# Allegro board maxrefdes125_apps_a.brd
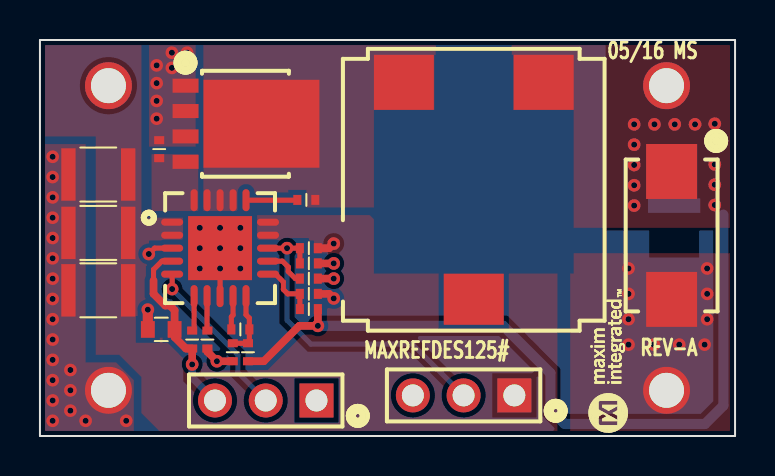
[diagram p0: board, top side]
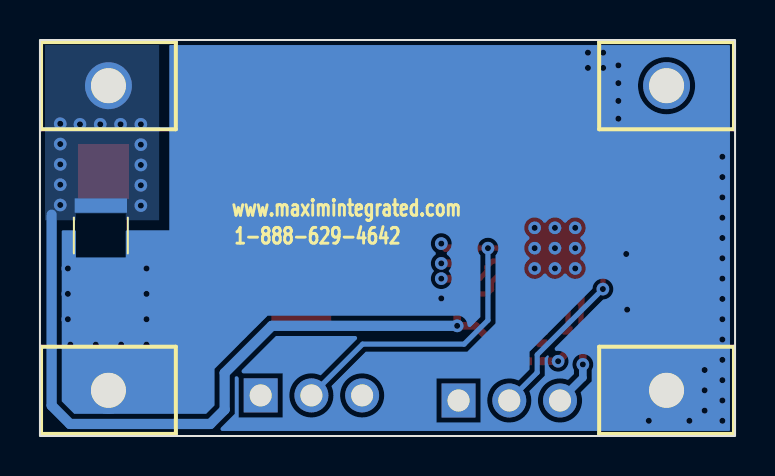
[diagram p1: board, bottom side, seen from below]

Outline 34.8 x 19.81 mm; copper layers: TOP, INTERNAL2, INTERNAL3, BOTTOM. Coordinates in mm from the lower left corner of the outline.
Outline path: rectangle 0,0 34.8,19.81

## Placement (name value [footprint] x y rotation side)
C1  2.2UF  [1210]  2.92 13.08 0 top
C2  2.2UF  [1210]  2.92 10.16 0 top
C3  OPEN  [1210]  2.92 7.29 0 top
C5  2.2UF  [0603]  6.07 5.33 0 top
C6  0.022UF  [0402]  13.46 7.87 0 top
C7  120UF  [CAPMP7343X310M]  31.62 10.03 270 top
C8  22UF  [1210]  31.75 10.03 90 bottom
C9  0.1UF  [0402]  13.34 11.81 0 top
C10  2.2PF  [0402]  10.03 5.33 180 top
C11  0.1UF  [0402]  13.46 7.11 180 top
EV_KIT_BOX2  MEDIUM BOX  [EVKIT_PACKAGING]  34.16 -5.33 0 top
GNDO  FWJ-01-01-T-S  [SAMTEC_FWJ-01-01-X-X]  31.37 2.29 270 bottom
JU1  PEC03SAAN  [SULLINS_PXC03S]  13.84 1.78 180 top
JU2  PEC03SAAN  [SULLINS_PXC03S]  23.75 2.03 180 top
L1  10UH  [IND_CEP125NP]  21.72 12.32 270 top
N1  RJK0651DPB-00#J5  [TO127P600X110-5M]  10.29 15.62 0 top
NOREF  -  []  25.15 52.2 0 top
NOREF#2  -  []  -12.19 19.81 0 top
NOREF#3  -  []  28.45 1.14 90 top
NOREF#4  -  []  47.37 19.81 0 top
NOREF#5  -  []  34.8 0 90 top
NOREF#6  -  []  124.71 -17.53 0 top
NOREF#7  -  []  46.86 0 0 top
NOREF#8  -  []  0 19.81 0 top
NOREF#9  -  []  12.7 -6.6 0 top
PGND  FWJ-01-01-T-S  [SAMTEC_FWJ-01-01-X-X]  3.43 2.29 270 bottom
R1  3.32M  [0402]  13.46 9.4 180 top
R2  300K  [0402]  13.46 8.64 0 top
R3  169K  [0402]  10.41 4.19 270 top
R4  36K  [0402]  9.65 4.19 270 top
R5  93.1K  [0402]  8.38 4.83 270 top
R6  10K  [0402]  7.62 4.83 90 top
R7  OPEN  [0402]  5.97 14.35 270 top
R8  4.7  [0402]  13.46 6.35 0 top
SU1  STC02SYAN  [EVKIT_SHUNT]  34.29 -12.32 0 top
SU2  STC02SYAN  [EVKIT_SHUNT]  34.16 -19.68 0 top
U1  MAX17536ATP+  [QFN65P500X500X80-21M]  9.02 9.4 0 top
VIN  FWJ-01-01-T-S  [SAMTEC_FWJ-01-01-X-X]  3.43 17.53 90 bottom
VOUT  FWJ-01-01-T-S  [SAMTEC_FWJ-01-01-X-X]  31.37 17.53 90 bottom

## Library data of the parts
C1 C2 = CAP_NP: alternate symbols: CAPC3225X270L; part number: CAP_NP_1210CAP-1210,2.2UF,20-002U2-Q1
C3 = EVK_GENERIC_CAPACITORS: alternate symbols: CAPC3225X270L; part number: EVK_GENERIC_CAPACITORS_1210CAP-1210,N/A
C5 = CAP_NP: alternate symbols: 0603_NOSILK,CAPC1608X90L; part number: CAP_NP_0603CAP-0603,2.2UF,20-002U2-10
C6 = CAP_NP: alternate symbols: 0402_NOSILK,CAPC1005X50L; part number: CAP_NP_0402CAP-0402,0.022UF,20-0U022-B60
C7 = CAP_POL: part number: CAP_POL_7343CAP-CAPMP7343X310M,120UF,20-0120U-J3A
C8 = CAP_NP: alternate symbols: CAPC3225X270L; part number: CAP_NP_1210CAP-1210,22UF,20-0022U-T7A
C9 C11 = CAP_NP: alternate symbols: 0402_NOSILK,CAPC1005X50L; part number: CAP_NP_0402CAP-0402,0.1UF,20-000U1-04A
C10 = CAP_NP: alternate symbols: 0402_NOSILK,CAPC1005X50L; part number: CAP_NP_0402CAP-0402,2.2PF,20-002P2-X1B
EV_KIT_BOX2 = EV_KIT_BOX: part number: EV_KIT_BOX_ACCESSORY-N/A,MEDIUM BOX,EVKIT_PACKAGING
GNDO PGND VIN VOUT = HEADER_1P: part number: HEADER_1P_TH-SAMTEC_FWJ-01-01-X-X,FWJ-01-01-T-S,01-FWJ0101TS1P-19
JU1 JU2 = HEADER_3P: alternate symbols: SULLINS_PXC03SL; part number: HEADER_3P_PXC03S-SULLINS_PXC03S,PEC03SAAN,01-PEC03SAAN3P-21
L1 = INDUCTOR_3P: part number: INDUCTOR_3P_IND_CEP125NP-IND_CEP125NP,10UH,50-0010U-0JG
N1 = TRAN_NCH_5P: part number: TRAN_NCH_5P_LFPAK-TO127P600X110-5M,RJK0651DPB-00#J5,90-RJK0651DPB00J5-21
R1 = RES: alternate symbols: (0402_NOSILK,RESC1005X50L); part number: RES_0402RES-0402,3.32M,80-03M32-23
R2 = RES: alternate symbols: (0402_NOSILK,RESC1005X50L); part number: RES_0402RES-0402,300K,80-0300K-23
R3 = RES: alternate symbols: (0402_NOSILK,RESC1005X50L); part number: RES_0402RES-0402,169K,80-0169K-23
R4 = RES: alternate symbols: 0402_NOSILK,RESC1005X50L; part number: RES_0402RES-0402,36K,80-0036K-18
R5 = RES: alternate symbols: (0402_NOSILK,RESC1005X50L); part number: RES_0402RES-0402,93.1K,80-093K1-23
R6 = RES: alternate symbols: 0402_NOSILK,RESC1005X50L; part number: RES_0402RES-0402,10K,80-0010K-23
R7 = EVK_GENERIC_RESISTORS: alternate symbols: 0402_NOSILK,RESC1005X50L; part number: EVK_GENERIC_RESISTORS_0402RES-0402,N/A
R8 = RES: alternate symbols: (0402_NOSILK,RESC1005X50L); part number: RES_0402RES-0402,4.7,80-004R7-23
SU1 SU2 = SHUNT: part number: SHUNT_SHUNT_2P-02-JMPFSTC02SYAN-00,STC02SYAN,EVKIT_SHUNT
U1 = EK_MAX17536: part number: EK_MAX17536_TQFN20-EP-QFN65P500X500X80-21M,MAX17536ATP+,N/A

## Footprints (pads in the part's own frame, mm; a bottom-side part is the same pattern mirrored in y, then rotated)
0402
  rect 0.4x0.5 smd: 1(-0.45,0) 2(0.45,0)
0603
  rect 0.69x0.83 smd: 1(-0.67,0) 2(0.67,0)
1210
  rect 0.72x2.62 smd: 1(-1.495,0) 2(1.495,0)
CAPMP7343X310M
  rect 2.75x2.55 smd: 1(-3.2,0) 2(3.2,0)
IND_CEP125NP
  rect 2.75x3 smd: 1(-5.375,3.5) 2(-5.375,-3.5)
  rect 2.55x3 smd: 3(5.475,0)
QFN65P500X500X80-21M
  oval 1.1x0.35 smd: 1(-2.4,1.3) 2(-2.4,0.65) 3(-2.4,0) 4(-2.4,-0.65) 5(-2.4,-1.3) 11(2.4,-1.3) 12(2.4,-0.65) 13(2.4,0) 14(2.4,0.65) 15(2.4,1.3)
  oval 0.35x1.1 smd: 6(-1.3,-2.4) 7(-0.65,-2.4) 8(0,-2.4) 9(0.65,-2.4) 10(1.3,-2.4) 16(1.3,2.4) 17(0.65,2.4) 18(0,2.4) 19(-0.65,2.4) 20(-1.3,2.4)
  rect 3.2x3.2 smd: 21(0,0)
SAMTEC_FWJ-01-01-X-X
  round 2.35 hole 1.75: 1(0,0)
SULLINS_PXC03S
  rect 1.7x1.7 hole 1.1: 1(0,0)
  round 1.7 hole 1.1: 2(2.54,0) 3(5.08,0)
TO127P600X110-5M
  rect 1.3x0.7 smd: 1(-3,1.905) 2(-3,0.635) 3(-3,-0.635) 4(-3,-1.905)
  rect 5.8x4.4 smd: 5(0.8,0)

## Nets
PGND: C1.1 C2.1 C3.1 C7.2(B) C8.1 C11.1 GNDO.1 N1.1(S1) N1.2(S2) N1.3(S3) PGND.1 R7.1 U1.3(PGND)
SGND: C5.1 C6.2 JU1.1 JU2.3 R2.2 R4.2 R5.2 U1.8(SGND) U1.21(EP)
VCC: C5.2 JU1.3 R6.1 U1.4(VCC)
VIN: C1.2 C2.2 C3.2 JU2.1 R1.1 U1.1(VIN_1) U1.2(VIN_2) U1.14(VIN_3) U1.15(VIN_4) VIN.1
UNNAMED_1_CAPNP_I5_2: C11.2 R8.1 U1.11(EXTVCC)
UNNAMED_1_CAPNP_I8_1: C6.1 U1.12(SS)
UNNAMED_1_CAPNP_I36_1: C9.1 U1.16(BST)
UNNAMED_1_CAPNP_I36_2: C9.2 L1.2 N1.5(D) U1.17(LX_1) U1.18(LX_2) U1.19(LX_3)
UNNAMED_1_CAPNP_I47_1: C10.1 R3.1 R4.1 U1.10(FB)
UNNAMED_1_CAPNP_I47_2: C10.2 U1.9(CF)
UNNAMED_1_EKMAX17536_I1_DL: N1.4(G) R7.2 U1.20(DL)
UNNAMED_1_EKMAX17536_I1_EN: JU2.2 R1.2 R2.1 U1.13(EN/UVLO)
UNNAMED_1_EKMAX17536_I1_MODE: JU1.2 U1.5(MODE/SYNC)
UNNAMED_1_EKMAX17536_I1_RESETB: R6.2 U1.6(RESETB)
UNNAMED_1_EKMAX17536_I1_RT: R5.1 U1.7(RT)
VOUT: C7.1(A) C8.2 L1.1 R3.2 R8.2 VOUT.1

Pads without a net: L1 3

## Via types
v1: diameter 0.635, hole 0.305, TOP to BOTTOM, 70 vias

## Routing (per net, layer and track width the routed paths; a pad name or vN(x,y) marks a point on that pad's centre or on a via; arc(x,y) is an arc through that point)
PGND: length 2.2
  TOP w0.254: v1(5.45,9.11) 5.74,9.4 U1.3
  TOP w0.381: v1(14.71,6.88) 14.48,7.11 C11.1
  vias: v1(0.64,13.97) v1(0.64,12.95) v1(0.64,11.94) v1(0.64,10.92) v1(0.64,9.91) v1(0.64,8.89) v1(0.64,7.87) v1(0.64,6.86) v1(0.64,5.84) v1(0.64,4.83) v1(0.64,3.81) v1(0.64,2.79) v1(0.64,1.78) v1(0.64,0.76) v1(1.52,3.3) v1(1.52,2.29) v1(1.52,1.27) v1(2.29,0.76) v1(4.32,0.76) v1(5.84,18.54) v1(5.84,17.65) v1(5.84,16.76) v1(5.84,15.88) v1(6.6,19.18) v1(6.6,18.41) v1(7.37,19.18) v1(7.37,18.41) v1(29.46,8.38) v1(29.46,7.11) v1(29.46,5.84) v1(29.46,4.57) v1(30.73,4.57) v1(32,4.57) v1(33.27,4.57) v1(33.4,8.38) v1(33.4,7.11) v1(33.4,5.84)
SGND: length 5.6
  TOP w0.254: v1(9.02,8.38) U1.8
  TOP w0.381: R5.2 8.38,4.22 v1(8.86,3.74) R4.2 ; C6.2 v1(14.71,7.87) ; R2.2 v1(14.71,8.64)
  TOP w0.508: C5.1 v1(5.4,6.32)
  vias: v1(8,10.41) v1(8,9.4) v1(8,8.38) v1(9.02,10.41) v1(9.02,9.4) v1(10.03,10.41) v1(10.03,9.4) v1(10.03,8.38)
VCC: length 9.2
  TOP w0.254: 5.69,7.78 5.69,8.33 6.11,8.75 U1.4
  TOP w0.381: 5.69,7.78 5.69,7.11 6.27,6.53 6.5,6.53 6.74,6.29 C5.2 6.74,4.95 7.31,4.38 R6.1 v1(7.62,3.58)
  BOTTOM w0.381: v1(7.62,3.58) 7.62,2.92 JU1.3
VIN: length 0.9
  TOP w0.381: v1(14.71,9.63) 14.48,9.4 R1.1
UNNAMED_1_CAPNP_I5_2: length 3
  TOP w0.254: R8.1 C11.2 12.4,7.11 12.19,7.33 12.19,7.7 11.79,8.1 U1.11
UNNAMED_1_CAPNP_I8_1: length 2.1
  TOP w0.254: U1.12 12.14,8.75 12.43,8.46 12.43,8.23 12.78,7.87 C6.1
UNNAMED_1_CAPNP_I36_1: length 2.6
  TOP w0.254: C9.1 12.87,11.8 U1.16
UNNAMED_1_CAPNP_I47_1: length 3.2
  TOP w0.254: U1.10 10.32,6.07 10.48,5.9 C10.1 10.48,4.71 R3.1 R4.1
UNNAMED_1_CAPNP_I47_2: length 1.7
  TOP w0.254: U1.9 9.67,6.05 9.58,5.97 C10.2
UNNAMED_1_EKMAX17536_I1_EN: length 16.4
  TOP w0.254: R2.1 R1.2 v1(12.37,9.4) U1.13
  BOTTOM w0.254: v1(12.37,9.4) 12.37,5.79 13.56,4.6 18.64,4.6 JU2.2
UNNAMED_1_EKMAX17536_I1_MODE: length 8.3
  TOP w0.254: U1.5 v1(6.62,7.35)
  BOTTOM w0.254: v1(6.62,7.35) 9.91,4.06 9.91,3.17 JU1.2
UNNAMED_1_EKMAX17536_I1_RESETB: length 1.8
  TOP w0.254: R6.2 7.72,5.37 U1.6
UNNAMED_1_EKMAX17536_I1_RT: length 1.7
  TOP w0.254: R5.1 8.37,5.29 U1.7
VOUT: length 38.4
  TOP w0.381: R8.2 v1(13.91,5.51) 12.98,5.51 11.21,3.74 R3.2
  BOTTOM w0.508: v1(13.91,5.51) 23.19,5.51 25.55,3.15 25.55,1.32 26.27,0.6 33.29,0.6 34.21,1.52 34.21,11.08
  vias: v1(29.75,15.59) v1(29.75,14.58) v1(29.75,13.56) v1(29.75,12.54) v1(29.75,11.53) v1(30.76,15.59) v1(31.78,15.59) v1(32.79,15.59) v1(33.78,15.62) v1(33.78,14.61) v1(33.78,13.59) v1(33.78,12.57) v1(33.78,11.56)

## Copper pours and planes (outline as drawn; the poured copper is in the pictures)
PGND on BOTTOM (solid shape): outline of 995 points within 0.25,0.25 33.71,19.56
PGND on TOP: 0.25,0.25 0.25,14.61 2.29,14.61 2.29,3.68 3.81,3.68 4.7,2.79 4.7,0.25 1.91,0.25 1.91,0.25
PGND on TOP: 5.46,14.48 5.46,19.56 8,19.56 8,14.48
PGND on TOP: 26.54,0.25 26.54,9.14 34.54,9.14 34.54,0.25
SGND on INTERNAL2, INTERNAL3: 0.26,0.26 0.26,19.56 34.54,19.56 34.54,0.26 ; 1 cut-out
VIN on TOP: 5.97,0.25 2.79,3.43 2.79,14.99 0.25,14.99 0.25,19.56 5.08,19.56 5.08,10.92 7.24,10.92 7.24,9.78 5.46,9.78 5.46,6.22 8,3.68 11.68,3.68 13.72,5.71 13.72,9.78 10.79,9.78 10.79,11.05 16.51,11.05 18.8,8.76 25.91,8.76 25.91,0.25
UNNAMED_1_CAPNP_I36_2 on TOP: 8.18,11.18 8.18,19.56 19.81,19.56 19.81,13.72 17.53,11.43 10.41,11.43 10.16,11.18
UNNAMED_1_EKMAX17536_I1_DL on TOP: 7.92,11.25 7.92,14.1 5.59,14.1 5.59,11.25
VOUT on TOP: 23.62,10.41 23.62,19.56 34.54,19.56 34.54,10.41
VOUT on BOTTOM: 28.83,10.79 28.83,19.56 34.54,19.56 34.54,10.79

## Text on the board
Ref Des/Silkscreen Bottom: 1-888-629-4642 | www.maximintegrated.com
Ref Des/Silkscreen Top: MAXREFDES125# | 05/16 MS | REV-A
DIMENSION: NOTES: | FINISH: | TESTING: | MISCELLANEOUS: | TOOLING: | 16.  VENDOR LOGO & DATE CODE REQUIRED IN INK ON BOTTOM SIDE ONLY. DATE CODE FORMAT MUST BE YYWW ONLY | 17.  FINAL ELECTRICAL TEST TO BE PERFORMED USING PROVIDED IPC-D-356A NETLIST OR ODB++ FORMAT FILE. | 18.  A TIME DOMAIN REFLECTOMETER REPORT FOR EACH IMPEDANCE CONTROLLED LAYER AND A CERTIFICATE | 15.  CHECK ALL THAT APPLY | 14.  CHECK ALL THAT APPLY | 19. IF PRESENT, ALL BLIND/BURIED VIAS WITH AN ASPECT RATIO <1:1 TO BE PLATED SHUT WITH COPPER WHEN | 20.  FOR ALL DRILL INFORMATION REFER TO DRILL CHART. | 21.  FINISHED SURFACE CONTACTS AND FILLED VIAS TO BE FREE OF ANY PITS. SCRATCHES PROBE MARKS | 23.  PEMNUT | 13.  DRILL SIZES ARE FINISHED HOLE SIZES. ALL HOLES SHALL BE LOCATED WITHIN .005 DTP. | 22.  THIEVING: | 9.  ALL TRACES FILLETED OPTION TO ENHANCE RELIABILITY AT PAD JUNCTIONS | 10.  LAYER TO LAYER REGISTRATIONS SHALL BE WITHIN .003 INCHES. | MATERIAL: | 11.  PLATING SPECIFICATION: | 12.  CHECK ALL THAT APPLY | 8.  IF STATED IN THE LAMINATION DIAGRAM, THE DIELECTRIC THICKNESS OF ANY | 1.  DIMENSIONS ARE IN INCHES (EXCEPT WHERE NOTED). | 3.  THE PCB SHALL BE FABRICATED TO IPC-6012, TYPE X, CLASS 2. | 4.  BOARD MATERIAL & CONSTRUCTION SHALL MEET THE REQUIREMENTS OF UL796 | 5.  OVERALL BOARD THICKNESS REFER TO LAMINATION DIAGRAM. TOLERANCE APPLIES | 6.  BOW & TWIST NOT TO EXCEED 0.0075 IN. (0.75%) PER LINEAR INCH. | 7.  PHOTO ETCH CIRCUITRY PER ENCLOSED GERBER RS274X OR ODB++ FORMAT FILE. | 2.  BOARD MATERIAL: | ( )  FINISH CONDUCTOR SURFACES: IMMERSION GOLD, 2-5 MICRO INCHES OVER | ( )  STARTING COPPER WEIGHT FOR OUTER LAYERS TO BE (1 OZ), THE FINISH COPPER WEIGHT IS (1 OZ). | ( )  STARTING COPPER WEIGHT FOR OUTER LAYERS TO BE (1 OZ), THE FINISH COPPER WEIGHT IS (2 OZ). | (X)  STARTING COPPER WEIGHT FOR OUTER LAYERS TO BE (2 OZ), THE FINISH COPPER WEIGHT IS (2 OZ)MINIMUM. | ( )  OTHER ________________________ | (X)  FINISH CONDUCTOR SURFACES: IMMERSION GOLD, 3-8 MICRO INCHES OVER | ( )  FINGERS TO BE GOLD PLATED. | ( )  LEAD FREE AND RoHS COMPLIANT PLATING. | (X)  GREEN SOLDERMASK OVER BARE COPPER/BARE GOLD (BOTH SIDES) WITH LIQUID PHOTO IMAGEABLE INK (LPI) | ( )  GREEN TAIYO PSR-4000 | ( )  ELECTRODEPOSITED HARD GOLD PLATE, TYPE 1 (99.7% MIN GOLD), GRADE C | (X)  APPLY SILKSCREEN USING A NON-CONDUCTIVE, WHITE EPOXY | THE STARTING WEIGHT CAN BE (0.5 OZ) AS LONG AS THE FINISH COPPER WEIGHT IS (2 OZ). | THE STARTING WEIGHT CAN BE (<2 OZ) AS LONG AS THE FINISH COPPER WEIGHT IS (2 OZ). | MINIMUM BARREL PLATING OF .001 IN. PLATED HOLES SHALL NOT BE ROUGH OR IRREGULAR | SO AS TO HINDER PROPER SOLDER WICKING. | USED AS VIA-IN PAD OR AS A STACKED VIA. BLIND/BURIED VIAS WITH AN ASPECT RATIO >1:1 TO BE FILLED | WITH NON-CONDUCTIVE EPOXY. UNLESS OTHERWISE SPECIFIED. | ( )  NON-CONDUCTIVE EPOXY. FILL AND CAP ALL 0.XXXX INCH DRILLED VIAS. | ( )  SILVER. FILL AND CAP ALL 0.XXXX INCH DRILLED VIAS. | (REQUIRED UNLESS OTHERWISE SPECIFIED IN QUOTE) | THE PCB SHALL HAVE A VERIFICATION STAMP. | OR OTHER DEFORMITIES THAT COULD EFFECT THE APPERANCE AND PERFORMACE OF THE CONTACT | SURFACE. CONTACTS ARE TO BE AS FLAT AS POSSIBLE. NOT TO EXCEED +/- 0.001" OF FLATNESS. | OF COMPLIANCE SHALL BE PROVIDED BY VENDOR AT TIME OF SHIPMENT. INSTANCES WHERE TDR TESTING | CAN'T BE PERFORMED BECAUSE THE TRACE LENGTH IS TOO SHORT ON THE OUTER LAYERS AT THE PIN ESCAPES | IS ACCEPTABLE, ALL OTHER INSTANCES MUST BE REPORTED. | ( )  SUPPLIER MAY ADD THIEVING TO COMPENSATE FOR LOW COPPER DENSITY AREAS ON THIS DESIGN. | WHERE SPACING PERMITS. | LEGEND TO LEGEND +/- 0.007 INCHES | (X)  SUPPLIER MAY NOT ADD THIEVING TO COMPENSATE FOR LOW COPPER DENSITY AREAS ON THIS DESIGN. | ( )  PEMNUTS TO BE INSTALLED BY SUPPLIER. | ( )  PEMNUTS NOT TO BE INSTALLED BY SUPPLIER. | (X)  NOT APPLICABLE | CONTROLLED IMPEDANCE LAYER IS FOR REFERENCE ONLY. FINAL ACCEPTANCE | SHALL BE DETERMINED BY THESE LAYERS HAVING A CHARACTERISTIC | IMPEDANCE OF +/-10% OHMS AS STATED IN THE LAMINATION DIAGRAM. THE | VENDOR CAN MAKE ADJUSTMENTS AS LONG AS THE STATED IMPEDANCE AND | OVERALL BOARD THICKNESS IS MAINTAINED. ANY ADJUSTMENT MADE TO TRACE | WIDTH OR SPACING MUST HAVE PRIOR WRITTEN APPROVAL FROM MAXIM. | ( )  FILLETED | (X)  NOT FILLETED | (X)  ISOLA 370HR OR EQUIVALENT | ( )  NELCO-4000-13 | ( )  MEGTRON 6 | ( )  ROGERS 4350B | ( )  ROGERS 4003C | ( )  ISOLA-FR408HR OR EQUIVALENT | WORKMANSHIP SHALL CONFORM TO IPC-A-600, CLASS 2, CURRENT REVISIONS. | WITH FLAMMABILITY RATING OF 94V-O. | AFTER ALL LAMINATION AND PLATING PROCESSES. IT IS TO BE MEASURED FROM | TOP PCB METAL TO BOTTOM PCB METAL UNLESS OTHERWISE SPECIFIED. | BOW & TWIST SHOULD BE MEASURED PER IPC-TM-650, METHOD 2.4.22. | DRILL LOCATION AND SIZE CONTROLLED BY EXCELLON CNC DRILL FILE. | FOR OUTER LAYERS WHERE SPACING PREVENTS THE USE OF (1 OZ) AS A STARTING WEIGHT, | FOR OUTER LAYERS WHERE SPACING PREVENTS THE USE OF (2 OZ) AS A STARTING WEIGHT, | UNLESS OTHERWISE SPECIFIED | FOR OUTER LAYERS WHERE SPACING PREVENTS THE USE OF (1 OZ) AS A STARTING WEIGHT | THE STARTING WEIGHT CAN BE (0.5 OZ) AS LONG AS THE FINISH COPPER WEIGHT IS (1 OZ) | (KNOOP HARDNESS 130-200), CLASS 1 (50-100 MICRO INCHES THICK) IN ACCORDANCE WITH MIL-G-45204C. | GENERAL SURFACING REQUIREMENTS MUST MEET ANSI/IPC-A-600(CURRENT REV) SECTION 4.0, | CLASS 3 (50-100 MICROINCHES THICK) OVER ELECTRODEPOSITED NICKEL PLATE | IN ACCORDANCE WITH ANSI/IPC-A-600D, SECTION 4.0, CLASS 3 (200-600 MICROINCHES THICK). | 100 MICRO INCHES MINIMUM OF ELECTROLESS NICKEL. | 118-236 MICRO INCHES MINIMUM OF ELECTROLESS NICKEL. | PER ARTWORK. | BASED INK PER ARTWORK. | (USE CHECKED ITEMS FOR MATERIAL) | (USE CHECKED ITEMS FOR PLATING) | (USE CHECKED ITEMS FOR TOOLING) | UNLESS OTHERWISE SPECIFIED: | VINCENT LI | XX/XX/2016 | MAXREFDES125_APPS_A
User.25: FIGURE | SIZE | 12.0 | 43.31 | 68.9 | TOLERANCE | +3.0/-10.0 | +3.0/-3.0 | PLATED | ALL UNITS ARE IN MILS | QTY | 70 | 6 | 4 | NOTES | DRILL CHART: TOP to BOTTOM
